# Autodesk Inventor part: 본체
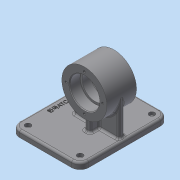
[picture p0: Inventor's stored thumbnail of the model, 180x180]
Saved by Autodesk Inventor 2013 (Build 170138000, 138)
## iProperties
Created: 2019-09
Part Number: 본체
Material: 일반
Document SubType Name: Modeling
Designer: Administrator
Density: 1 g/cm^3
Author: Administrator
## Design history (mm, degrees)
sketch "스케치1"
  geometry: C1 r 32 at (0, 0); 1 further point
  constraints: 1 centre point, 1 coincident
  dimensions: "d0" = 64 diameter of C1
extrude "돌출1" new body sketch "스케치1" stored distance "d1" = 42; taper "d2" = 0 deg
hole "구멍1" diameter "d5" = 36; stored, may be unused: countersink angle "d9" = 90 deg, drill point angle "d11" = 118 deg; dims "d6" = 6, "d7" = 42, "d8" = 15, "d10" = 8, "d12" = 10, "d13" = 10
sketch "스케치2"
  geometry: C1 r 18 at (0, 0) reference; C2 r 32 at (0, 0) reference; C3 r 21 at (0, 0)
  constraints: 1 centre point, 1 coincident
  dimensions: "d14" = 42 diameter of C3
extrude "돌출2" cut sketch "스케치2" distance "d15" = 15; taper "d16" = 0 deg
sketch "스케치3"
  geometry: C1 r 21 at (0, 0) reference; 1 further point
  constraints: 1 vertical alignment
  dimensions: "d17" = 26 distance of point (0, 26) C1.centre
hole "구멍2" sketch "스케치3" at (0, 26) diameter "d18" = 3.242; stored, may be unused: countersink angle "d22" = 90 deg, drill point angle "d24" = 118 deg; dims "d19" = 8, "d20" = 42, "d21" = 15, "d23" = 10
chamfer "모따기1" distance "d28" = 1; stored, may be unused: second distance "d29" = 2, angle "d30" = 45 deg
fillet "모깎기1" dims "d31" = 0.3
sketch "스케치4"
  geometry: L1 (-62, -50)-(36, -50); L2 (36, -50)-(36, -59); L3 (36, -59)-(-62, -59); L4 (-62, -59)-(-62, -50); 1 further point
  constraints: 8 end point, 2 parallel, 1 horizontal, 1 perpendicular
  dimensions: "d32" = 59 distance from line of L3 point (0, 0); "d33" = 9 distance of L1.end L2.end; "d34" = 98 distance of L2.end L3.end; "d35" = 36 distance from line of L2 point (0, 0)
extrude "돌출3" join sketch "스케치4" stored distance "d36" = 126; taper "d37" = 0 deg
fillet "모깎기2" dims "d38" = 12
fillet "모깎기3" dims "d39" = 3
sketch "스케치5"
  geometry: A1 r 9 centre (0, 9) between (-9, 9) and (0, 0) reference; A2 r 9 centre (74, 9) between (74, 0) and (83, 9) reference; A3 r 9 centre (74, 111) between (83, 111) and (74, 120) reference; A4 r 9 centre (0, 111) between (0, 120) and (-9, 111) reference; 5 further points
  constraints: 4 coincident
hole "구멍3" sketch "스케치5" at (0, 111), (74, 111), (0, 9), (74, 9) diameter "d40" = 4.5; stored, may be unused: countersink angle "d44" = 90 deg, drill point angle "d46" = 118 deg; dims "d41" = 8, "d42" = 8, "d43" = 4.4, "d45" = 10
sketch "스케치6"
  geometry: L1 (18, 64)-(82, 64); L2 (82, 64)-(82, 56); L3 (82, 56)-(18, 56); L4 (18, 56)-(18, 64); 2 further points
  constraints: 8 end point, 2 parallel, 1 horizontal, 1 horizontal alignment, 1 midpoint, 1 perpendicular
  dimensions: "d47" = 64 distance of L1.start L1.end; "d49" = 8 distance of L3.end L1.start; "d50" = 32 distance from line of point (50, 60) L2
extrude "돌출4" join sketch "스케치6" stored distance "d51" = 126; taper "d52" = 0 deg
sketch "스케치7"
  geometry: L1 (46, 43)-(54, 43); L2 (54, 43)-(54, 77); L3 (54, 77)-(46, 77); L4 (46, 77)-(46, 43); 3 further points
  constraints: 8 end point, 2 midpoint, 2 parallel, 1 horizontal, 1 horizontal alignment, 1 perpendicular, 1 vertical alignment
  dimensions: "d53" = 8 distance of L3.end L2.end; "d54" = 34 distance of L2.end L1.end
extrude "돌출5" join sketch "스케치7" stored distance "d55" = 126; taper "d56" = 0 deg
fillet "모깎기4" dims "d57" = 3
fillet "모깎기5" dims "d58" = 3
fillet "모깎기6" dims "d59" = 3
sketch "스케치8"
  geometry: L1 (74, 3)-(0, 3) reference; L2 (-12, -9)-(-12, -111) reference; 2 further points
  constraints: 1 other
  dimensions: "d60" = 63 distance from line of L1 point (-2, -60); "d61" = 10 distance from line of L2 point (-2, -60)
feature "엠보싱1" sketch "스케치8" dims "d62" = 0.5, "d63" = 0
node "솔리드1"
pattern_circular "원형 패턴1" dims angle "d26" = 360 deg
mirror "대칭1"
